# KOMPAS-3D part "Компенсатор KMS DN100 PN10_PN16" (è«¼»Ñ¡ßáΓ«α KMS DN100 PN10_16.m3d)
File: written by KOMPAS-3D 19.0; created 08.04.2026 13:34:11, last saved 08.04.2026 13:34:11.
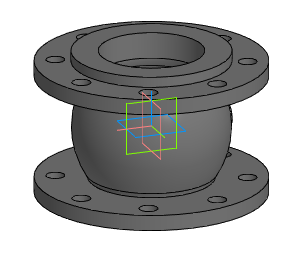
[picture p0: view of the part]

Document properties: Автор: Энергия; Полное имя файла: Z:\3.Личные\kachalov\3d для проектировщиков\7.1 Компенсатор\stp_Компенсатор KSM\Компенсатор KMS DN100 PN10_16.m3d

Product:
- Part/product: Компенсатор KMS DN100 PN10_PN16

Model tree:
1. Операция без истории:1  (labels: Компенсатор KMS DN100 PN10_PN16)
